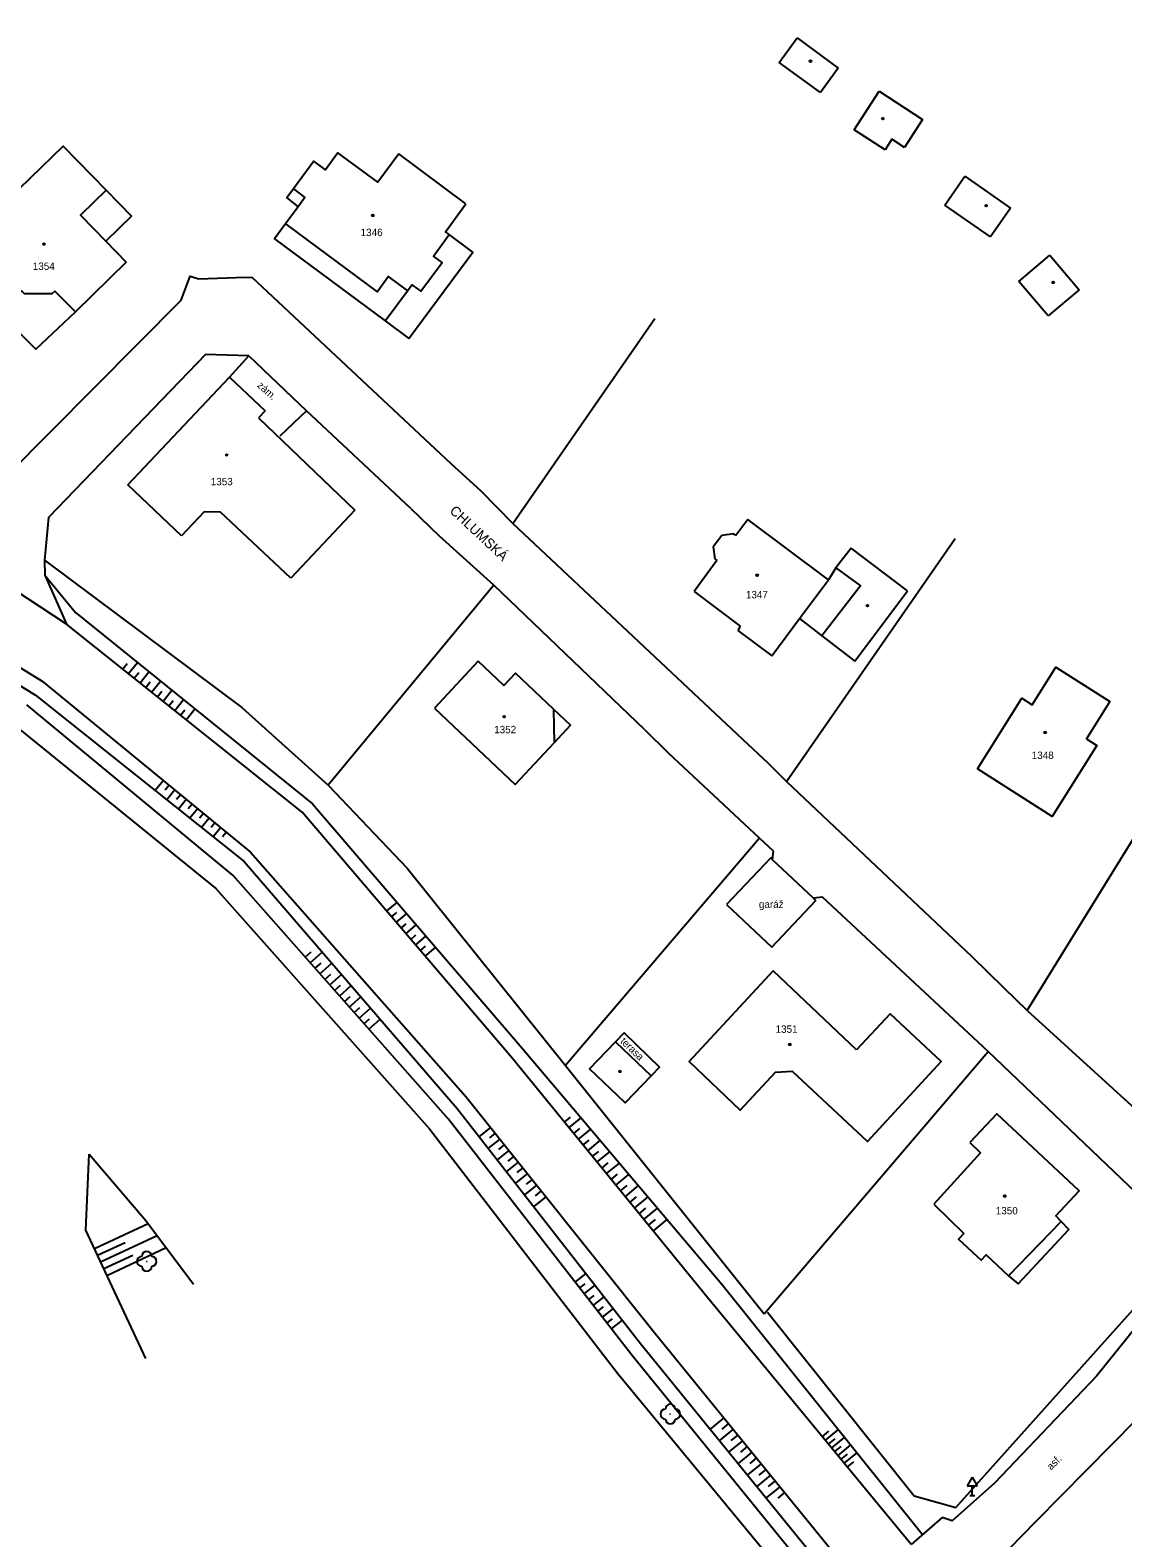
# Model space of a CAD drawing. Extents: x -794191 to -788944, y -1117087 to -1105044.
# Drawn here: x -792433.6 to -792322.7, y -1109251.7 to -1109098.8 of the extents above; entities that cross this region are included whole.
import ezdxf

# ---------------------------------------------------------------- set-up
doc = ezdxf.new("R2010")
doc.units = 0
for name, color, linetype in [('Doplňkové značky', 7, 'Continuous'), ('Hranice - ploty_ zdi', 7, 'Continuous'), ('Komunikace', 7, 'Continuous'), ('Názvy ulic_ silnic_ žel_', 7, 'Continuous'), ('Pomocné popisy', 7, 'Continuous'), ('Popisy budov', 7, 'Continuous'), ('Stavební objekty', 7, 'Continuous'), ('Výškopis', 7, 'Continuous'), ('Zeleň', 7, 'Continuous'), ('Značky druhů budov', 7, 'Continuous'), ('Čísla popisná', 7, 'Continuous')]:
    doc.layers.add(name, color=color, linetype=linetype)

msp = doc.modelspace()

# ---------------------------------------------------------------- linework, layer by layer
at = {"layer": 'Doplňkové značky'}
for p, q in [((-792337.99, -1109245.564), (-792338.49, -1109246.43)), ((-792338.49, -1109246.43), (-792337.49, -1109246.43)), ((-792337.99, -1109245.564), (-792337.49, -1109246.43)), ((-792337.99, -1109247.43), (-792337.99, -1109246.43)), ((-792338.24, -1109247.43), (-792337.74, -1109247.43))]:
    msp.add_line(p, q, dxfattribs=at)
at = {"layer": 'Hranice - ploty_ zdi'}
for p, q in [((-792416.47, -1109123.98), (-792412.69, -1109123.86)), ((-792384.6, -1109148.81), (-792370.19, -1109128.01)), ((-792413.37, -1109133.97), (-792411.38, -1109131.8)), ((-792390.89, -1109142.72), (-792387.85, -1109145.48)), ((-792387.85, -1109145.48), (-792384.6, -1109148.81)), ((-792394.94, -1109147.29), (-792392.04, -1109150.11)), ((-792384.6, -1109148.81), (-792361.29, -1109170.69)), ((-792386.55, -1109155.05), (-792392.04, -1109150.11)), ((-792356.84, -1109174.99), (-792339.72, -1109150.34)), ((-792332.43, -1109198.21), (-792314.33, -1109168.93)), ((-792371.26, -1109169.72), (-792368.8, -1109172.1)), ((-792361.29, -1109170.69), (-792358.7, -1109173.12)), ((-792359.57, -1109180.73), (-792368.8, -1109172.1)), ((-792358.7, -1109173.12), (-792356.84, -1109174.99)), ((-792356.84, -1109174.99), (-792338.03, -1109192.74)), ((-792359.57, -1109180.73), (-792379.27, -1109203.8)), ((-792358.17, -1109182.06), (-792359.57, -1109180.73)), ((-792358.27, -1109182.94), (-792358.17, -1109182.06)), ((-792354.11, -1109186.82), (-792358.27, -1109182.94)), ((-792353.19, -1109186.72), (-792354.11, -1109186.82)), ((-792336.37, -1109202.39), (-792353.19, -1109186.72)), ((-792362.92, -1109187.47), (-792358.33, -1109191.8)), ((-792338.03, -1109192.74), (-792334.83, -1109195.87)), ((-792334.83, -1109195.87), (-792332.43, -1109198.21)), ((-792332.43, -1109198.21), (-792319.56, -1109209.93)), ((-792359.09, -1109228.98), (-792336.37, -1109202.39)), ((-792379.27, -1109203.8), (-792359.09, -1109228.98))]:
    msp.add_line(p, q, dxfattribs=at)
for points in [[(-792435.9, -1109143.89), (-792418.26, -1109126.16), (-792417.35, -1109123.73), (-792416.47, -1109123.98)], [(-792412.69, -1109123.86), (-792411.09, -1109123.83), (-792390.89, -1109142.72)], [(-792411.38, -1109131.8), (-792415.78, -1109131.66), (-792431.74, -1109148.19), (-792432.13, -1109152.54)], [(-792394.94, -1109147.29), (-792405.54, -1109137.37), (-792408.24, -1109139.95)], [(-792432.13, -1109152.54), (-792412.1, -1109167.48), (-792403.34, -1109175.37)], [(-792371.26, -1109169.72), (-792386.55, -1109155.05), (-792403.34, -1109175.37)], [(-792403.34, -1109175.37), (-792395.34, -1109183.79), (-792379.27, -1109203.8)], [(-792358.27, -1109182.94), (-792358.44, -1109182.74), (-792362.92, -1109187.47)], [(-792358.33, -1109191.8), (-792353.9, -1109187.09), (-792354.11, -1109186.82)], [(-792374.18, -1109201.39), (-792373.3, -1109200.5), (-792369.71, -1109203.96), (-792370.56, -1109204.86)], [(-792317.22, -1109223.41), (-792316.83, -1109221.03), (-792336.37, -1109202.39)], [(-792358.77, -1109228.84), (-792343.87, -1109247.47), (-792339.66, -1109248.64), (-792319.89, -1109226.58)]]:
    msp.add_lwpolyline(points, dxfattribs=at)
at = {"layer": 'Komunikace'}
for p, q in [((-792411.38, -1109131.8), (-792405.54, -1109137.37)), ((-792447.38, -1109155.57), (-792432.36, -1109164.8)), ((-792432.36, -1109164.8), (-792411.21, -1109182.14)), ((-792411.21, -1109182.14), (-792389.39, -1109206.94)), ((-792315.92, -1109223.55), (-792325.38, -1109235.31))]:
    msp.add_line(p, q, dxfattribs=at)
for points in [[(-792344.2, -1109252.39), (-792364.9, -1109227.31), (-792384.65, -1109203.09), (-792405.99, -1109178.11), (-792429.89, -1109159.02), (-792436.53, -1109154.65), (-792444.12, -1109150.51), (-792463.48, -1109139.83), (-792485.49, -1109128.03), (-792502.16, -1109119.01), (-792513.91, -1109112.56), (-792525.39, -1109106.43), (-792542.08, -1109097.39), (-792570.53, -1109082.24), (-792594.12, -1109069.43), (-792609.89, -1109060.71), (-792628.36, -1109050.84), (-792647.56, -1109040.71)], [(-792432.13, -1109152.54), (-792432.1, -1109154.04), (-792429.89, -1109159.02)], [(-792389.39, -1109206.94), (-792370.12, -1109231.03), (-792348.83, -1109257.2), (-792332.86, -1109277.6), (-792324.34, -1109288.15)], [(-792337.34, -1109261.8), (-792337.76, -1109260.31), (-792337.77, -1109258.92), (-792337.53, -1109257.73), (-792336.95, -1109255.61), (-792331.49, -1109250.02), (-792321.28, -1109239.69), (-792309.93, -1109226.65), (-792306.29, -1109222.44)], [(-792325.38, -1109235.31), (-792335.73, -1109246.18), (-792340.01, -1109250), (-792341.03, -1109249.65), (-792344.2, -1109252.39)]]:
    msp.add_lwpolyline(points, dxfattribs=at)
at = {"layer": 'Stavební objekty'}
for p, q in [((-792357.58, -1109102.02), (-792355.77, -1109099.53)), ((-792355.77, -1109099.53), (-792351.58, -1109102.6)), ((-792353.39, -1109105.07), (-792357.58, -1109102.02)), ((-792351.58, -1109102.6), (-792353.39, -1109105.07)), ((-792349.97, -1109108.86), (-792347.44, -1109104.96)), ((-792347.44, -1109104.96), (-792343.03, -1109107.83)), ((-792346.84, -1109110.89), (-792349.97, -1109108.86)), ((-792343.03, -1109107.83), (-792344.86, -1109110.65)), ((-792346.14, -1109109.81), (-792346.84, -1109110.89)), ((-792344.86, -1109110.65), (-792346.14, -1109109.81)), ((-792340.77, -1109116.52), (-792338.73, -1109113.56)), ((-792338.73, -1109113.56), (-792334.1, -1109116.81)), ((-792425.87, -1109114.98), (-792423.31, -1109117.62)), ((-792336.14, -1109119.71), (-792340.77, -1109116.52)), ((-792334.1, -1109116.81), (-792336.14, -1109119.71)), ((-792333.26, -1109124.26), (-792330.13, -1109121.57)), ((-792330.13, -1109121.57), (-792327.15, -1109125.09)), ((-792330.27, -1109127.73), (-792333.26, -1109124.26)), ((-792327.15, -1109125.09), (-792330.27, -1109127.73)), ((-792397.56, -1109128.23), (-792395.16, -1109130.03)), ((-792423.67, -1109144.88), (-792413.37, -1109133.97)), ((-792413.37, -1109133.97), (-792409.75, -1109137.39)), ((-792409.75, -1109137.39), (-792410.42, -1109138.09)), ((-792410.42, -1109138.09), (-792400.65, -1109147.44)), ((-792418.22, -1109150.05), (-792423.67, -1109144.88)), ((-792400.65, -1109147.44), (-792407.15, -1109154.37)), ((-792415.93, -1109147.62), (-792418.22, -1109150.05)), ((-792414.26, -1109147.65), (-792415.93, -1109147.62)), ((-792407.15, -1109154.37), (-792414.26, -1109147.65)), ((-792360.75, -1109148.4), (-792361.99, -1109150.04)), ((-792352.56, -1109154.51), (-792360.75, -1109148.4)), ((-792363.41, -1109150.04), (-792364.29, -1109151.18)), ((-792362.17, -1109149.87), (-792363.41, -1109150.04)), ((-792361.99, -1109150.04), (-792362.17, -1109149.87)), ((-792364.29, -1109151.18), (-792364.1, -1109152.41)), ((-792350.27, -1109151.3), (-792351.84, -1109153.31)), ((-792344.56, -1109155.65), (-792350.27, -1109151.3)), ((-792363.92, -1109152.56), (-792366.22, -1109155.71)), ((-792364.1, -1109152.41), (-792363.92, -1109152.56)), ((-792351.84, -1109153.31), (-792352.56, -1109154.51)), ((-792355.5, -1109158.46), (-792352.56, -1109154.51)), ((-792366.22, -1109155.71), (-792361.53, -1109159.23)), ((-792349.89, -1109162.76), (-792344.56, -1109155.65)), ((-792361.53, -1109159.23), (-792361.78, -1109159.67)), ((-792361.78, -1109159.67), (-792358.31, -1109162.25)), ((-792358.31, -1109162.25), (-792355.5, -1109158.46)), ((-792355.5, -1109158.46), (-792353.25, -1109160.22)), ((-792353.25, -1109160.22), (-792349.89, -1109162.76)), ((-792380.48, -1109167.63), (-792380.4, -1109171.05)), ((-792374.18, -1109201.39), (-792370.56, -1109204.86))]:
    msp.add_line(p, q, dxfattribs=at)
for points in [[(-792423.83, -1109122.29), (-792428.99, -1109127.35), (-792431.09, -1109125.24), (-792431.4, -1109125.5), (-792434.15, -1109125.51), (-792434.48, -1109125.21), (-792436.77, -1109127.44), (-792440.51, -1109123.66), (-792439.92, -1109123.03), (-792437.74, -1109120.94), (-792438.5, -1109120.15), (-792434.99, -1109116.7), (-792435.78, -1109115.91), (-792430.23, -1109110.53), (-792425.87, -1109114.98), (-792428.48, -1109117.51), (-792425.91, -1109120.15)], [(-792396.19, -1109111.32), (-792398.3, -1109114.17), (-792402.35, -1109111.19), (-792403.62, -1109112.91), (-792404.8, -1109112.05), (-792406.88, -1109114.87), (-792405.71, -1109115.75), (-792406.4, -1109116.69), (-792407.68, -1109118.42), (-792398.39, -1109125.29), (-792397.25, -1109123.76), (-792395.29, -1109125.21), (-792394.84, -1109124.59), (-792393.94, -1109125.24), (-792391.79, -1109122.32), (-792392.64, -1109121.68), (-792391.07, -1109119.5), (-792391.44, -1109119.21), (-792389.37, -1109116.38)], [(-792389.37, -1109116.38), (-792396.19, -1109111.32)], [(-792406.88, -1109114.87), (-792407.54, -1109115.78), (-792406.4, -1109116.69)], [(-792423.31, -1109117.62), (-792425.91, -1109120.15), (-792423.83, -1109122.29)], [(-792407.68, -1109118.42), (-792408.8, -1109119.94), (-792397.56, -1109128.23), (-792395.29, -1109125.21)], [(-792395.16, -1109130.03), (-792388.68, -1109121.27), (-792391.07, -1109119.5)], [(-792436.77, -1109127.44), (-792433, -1109131.11), (-792428.99, -1109127.35)], [(-792351.84, -1109153.31), (-792349.33, -1109155.12), (-792353.25, -1109160.22)], [(-792388.14, -1109162.79), (-792392.56, -1109167.54)], [(-792392.56, -1109167.54), (-792384.37, -1109175.28), (-792380.4, -1109171.05), (-792378.74, -1109169.27), (-792380.48, -1109167.63), (-792384.35, -1109164.01), (-792385.52, -1109165.23), (-792388.14, -1109162.79)], [(-792358.18, -1109194.21), (-792366.7, -1109203.4), (-792361.55, -1109208.32), (-792357.94, -1109204.46), (-792356.26, -1109204.39), (-792348.63, -1109211.52), (-792341.13, -1109203.38), (-792346.32, -1109198.57), (-792349.72, -1109202.22)], [(-792349.72, -1109202.22), (-792358.18, -1109194.21)], [(-792370.56, -1109204.86), (-792373.22, -1109207.59), (-792376.83, -1109204.13), (-792374.18, -1109201.39)], [(-792341.9, -1109217.86), (-792338.85, -1109220.85), (-792339.37, -1109221.41), (-792337.07, -1109223.56), (-792336.56, -1109223.02), (-792334.3, -1109225.15), (-792333.32, -1109225.95), (-792328.17, -1109220.45), (-792328.98, -1109219.61), (-792329.52, -1109219.05), (-792327.13, -1109216.51), (-792335.49, -1109208.69), (-792338.23, -1109211.6)], [(-792338.23, -1109211.6), (-792337.14, -1109212.65), (-792341.9, -1109217.86)], [(-792334.3, -1109225.15), (-792328.98, -1109219.61)]]:
    msp.add_lwpolyline(points, dxfattribs=at)
msp.add_lwpolyline([(-792337.47, -1109173.71), (-792332.96, -1109166.54), (-792331.9, -1109167.19), (-792329.5, -1109163.38), (-792324.02, -1109166.87), (-792326.4, -1109170.67), (-792325.36, -1109171.34), (-792329.89, -1109178.53)], close=True, dxfattribs=at)
at = {"layer": 'Výškopis'}
for p, q in [((-792448.18, -1109156.9), (-792433.05, -1109166.21)), ((-792424.19, -1109163.57), (-792423.74, -1109163)), ((-792423.61, -1109164.04), (-792422.7, -1109162.91)), ((-792423.02, -1109164.51), (-792422.57, -1109163.94)), ((-792422.43, -1109164.97), (-792421.54, -1109163.85)), ((-792421.85, -1109165.44), (-792421.4, -1109164.88)), ((-792421.26, -1109165.91), (-792420.37, -1109164.79)), ((-792420.68, -1109166.38), (-792420.23, -1109165.82)), ((-792420.09, -1109166.85), (-792419.2, -1109165.73)), ((-792413, -1109184.53), (-792433.93, -1109167.21)), ((-792433.05, -1109166.21), (-792411.87, -1109183.11)), ((-792419.5, -1109167.31), (-792419.06, -1109166.76)), ((-792418.92, -1109167.78), (-792418.03, -1109166.67)), ((-792418.33, -1109168.25), (-792417.89, -1109167.7)), ((-792417.75, -1109168.72), (-792416.87, -1109167.62)), ((-792420.05, -1109174.89), (-792420.89, -1109175.91)), ((-792419.47, -1109175.37), (-792419.89, -1109175.87)), ((-792418.89, -1109175.84), (-792419.72, -1109176.85)), ((-792418.31, -1109176.32), (-792418.72, -1109176.82)), ((-792417.73, -1109176.79), (-792418.54, -1109177.78)), ((-792417.15, -1109177.27), (-792417.55, -1109177.76)), ((-792416.57, -1109177.74), (-792417.37, -1109178.72)), ((-792415.99, -1109178.22), (-792416.39, -1109178.7)), ((-792415.41, -1109178.69), (-792416.2, -1109179.66)), ((-792414.83, -1109179.17), (-792415.22, -1109179.65)), ((-792414.25, -1109179.65), (-792415.03, -1109180.59)), ((-792413.67, -1109180.12), (-792414.06, -1109180.59)), ((-792411.87, -1109183.11), (-792390.25, -1109208.16)), ((-792391.17, -1109209.22), (-792413, -1109184.53)), ((-792397.41, -1109188.15), (-792396.35, -1109187.25)), ((-792396.92, -1109188.73), (-792396.39, -1109188.27)), ((-792396.43, -1109189.29), (-792395.37, -1109188.39)), ((-792395.95, -1109189.87), (-792395.42, -1109189.41)), ((-792395.46, -1109190.44), (-792394.4, -1109189.53)), ((-792394.97, -1109191.01), (-792394.44, -1109190.55)), ((-792394.49, -1109191.58), (-792393.42, -1109190.67)), ((-792394, -1109192.15), (-792393.47, -1109191.69)), ((-792393.51, -1109192.72), (-792392.44, -1109191.81)), ((-792405.67, -1109192.81), (-792405.06, -1109192.27)), ((-792405.18, -1109193.38), (-792403.95, -1109192.29)), ((-792404.68, -1109193.94), (-792404.07, -1109193.4)), ((-792404.19, -1109194.5), (-792402.97, -1109193.42)), ((-792403.69, -1109195.06), (-792403.08, -1109194.53)), ((-792403.19, -1109195.62), (-792401.99, -1109194.56)), ((-792402.69, -1109196.19), (-792402.1, -1109195.66)), ((-792402.2, -1109196.75), (-792401.01, -1109195.69)), ((-792401.7, -1109197.31), (-792401.11, -1109196.79)), ((-792401.2, -1109197.87), (-792400.03, -1109196.83)), ((-792400.71, -1109198.43), (-792400.12, -1109197.92)), ((-792400.21, -1109198.99), (-792399.05, -1109197.97)), ((-792399.71, -1109199.56), (-792399.14, -1109199.05)), ((-792399.22, -1109200.12), (-792398.07, -1109199.1)), ((-792390.25, -1109208.16), (-792371.65, -1109231.99)), ((-792372.39, -1109233.34), (-792391.17, -1109209.22)), ((-792386.87, -1109210.09), (-792388.03, -1109211.01)), ((-792379.38, -1109209.55), (-792378.77, -1109209.05)), ((-792378.91, -1109210.13), (-792377.67, -1109209.12)), ((-792378.43, -1109210.71), (-792377.81, -1109210.2)), ((-792385.93, -1109211.26), (-792387.1, -1109212.19)), ((-792386.4, -1109210.67), (-792386.98, -1109211.14)), ((-792377.96, -1109211.29), (-792376.7, -1109210.27)), ((-792377.49, -1109211.87), (-792376.85, -1109211.36)), ((-792377.01, -1109212.45), (-792375.73, -1109211.41)), ((-792427.94, -1109220.52), (-792427.6, -1109212.81)), ((-792427.6, -1109212.81), (-792421.84, -1109219.53)), ((-792385, -1109212.43), (-792386.18, -1109213.37)), ((-792385.47, -1109211.84), (-792386.05, -1109212.31)), ((-792384.53, -1109213.02), (-792385.12, -1109213.49)), ((-792376.54, -1109213.04), (-792375.89, -1109212.51)), ((-792376.07, -1109213.62), (-792374.77, -1109212.56)), ((-792384.06, -1109213.6), (-792385.26, -1109214.56)), ((-792383.12, -1109214.77), (-792384.33, -1109215.74)), ((-792383.59, -1109214.19), (-792384.19, -1109214.67)), ((-792375.59, -1109214.2), (-792374.94, -1109213.66)), ((-792375.12, -1109214.78), (-792373.79, -1109213.7)), ((-792374.64, -1109215.36), (-792373.98, -1109214.82)), ((-792382.19, -1109215.94), (-792383.41, -1109216.92)), ((-792382.66, -1109215.36), (-792383.26, -1109215.85)), ((-792374.17, -1109215.94), (-792372.83, -1109214.85)), ((-792373.69, -1109216.52), (-792373.02, -1109215.97)), ((-792373.22, -1109217.11), (-792371.86, -1109215.99)), ((-792381.25, -1109217.12), (-792382.49, -1109218.11)), ((-792381.72, -1109216.53), (-792382.33, -1109217.02)), ((-792372.75, -1109217.69), (-792372.06, -1109217.13)), ((-792372.27, -1109218.27), (-792370.89, -1109217.14)), ((-792371.8, -1109218.85), (-792371.1, -1109218.28)), ((-792371.33, -1109219.43), (-792369.92, -1109218.28)), ((-792421.85, -1109233.54), (-792427.94, -1109220.52)), ((-792427.07, -1109222.37), (-792421.62, -1109219.82)), ((-792421.84, -1109219.53), (-792417, -1109225.98)), ((-792370.85, -1109220.01), (-792370.14, -1109219.43)), ((-792370.38, -1109220.59), (-792368.95, -1109219.43)), ((-792426.76, -1109223.05), (-792423.96, -1109221.74)), ((-792426.44, -1109223.73), (-792420.7, -1109221.05)), ((-792425.8, -1109225.09), (-792419.78, -1109222.27)), ((-792426.12, -1109224.41), (-792423.18, -1109223.04)), ((-792378.28, -1109225.78), (-792377.17, -1109224.91)), ((-792377.82, -1109226.37), (-792377.26, -1109225.94)), ((-792377.36, -1109226.96), (-792376.25, -1109226.1)), ((-792376.9, -1109227.55), (-792376.34, -1109227.12)), ((-792376.44, -1109228.14), (-792375.33, -1109227.28)), ((-792375.97, -1109228.74), (-792375.42, -1109228.3)), ((-792375.51, -1109229.33), (-792374.4, -1109228.46)), ((-792375.05, -1109229.92), (-792374.5, -1109229.49)), ((-792374.59, -1109230.51), (-792373.48, -1109229.65)), ((-792371.65, -1109231.99), (-792350.09, -1109258.51)), ((-792351.23, -1109259.36), (-792372.39, -1109233.34)), ((-792363.19, -1109239.55), (-792364.58, -1109240.69)), ((-792362.24, -1109240.71), (-792363.63, -1109241.85)), ((-792362.71, -1109240.13), (-792363.41, -1109240.7)), ((-792352.9, -1109241.85), (-792351.56, -1109240.74)), ((-792361.29, -1109241.88), (-792362.69, -1109243.01)), ((-792361.77, -1109241.3), (-792362.47, -1109241.86)), ((-792353.22, -1109241.46), (-792352.54, -1109240.9)), ((-792352.58, -1109242.23), (-792351.91, -1109241.68)), ((-792352.26, -1109242.62), (-792350.93, -1109241.52)), ((-792351.63, -1109243.39), (-792350.3, -1109242.3)), ((-792360.35, -1109243.04), (-792361.74, -1109244.18)), ((-792360.82, -1109242.46), (-792361.52, -1109243.03)), ((-792359.87, -1109243.62), (-792360.57, -1109244.19)), ((-792351.95, -1109243), (-792351.28, -1109242.46)), ((-792351.31, -1109243.78), (-792350.65, -1109243.23)), ((-792350.99, -1109244.16), (-792349.68, -1109243.08)), ((-792359.4, -1109244.21), (-792360.8, -1109245.34)), ((-792358.45, -1109245.37), (-792359.85, -1109246.5)), ((-792358.93, -1109244.79), (-792359.63, -1109245.35)), ((-792350.67, -1109244.55), (-792350.02, -1109244.01)), ((-792357.51, -1109246.53), (-792358.9, -1109247.67)), ((-792357.98, -1109245.95), (-792358.68, -1109246.52)), ((-792357.03, -1109247.11), (-792357.73, -1109247.68))]:
    msp.add_line(p, q, dxfattribs=at)
msp.add_lwpolyline([(-792432.1, -1109154.04), (-792428.99, -1109157.84), (-792404.93, -1109177.24), (-792383.67, -1109202.04), (-792363.39, -1109225.99), (-792343.02, -1109251.37)], dxfattribs=at)
at = {"layer": 'Zeleň'}
for p, q in [((-792435.9, -1109168.68), (-792414.75, -1109185.85)), ((-792414.75, -1109185.85), (-792393.07, -1109210.23)), ((-792393.07, -1109210.23), (-792373.97, -1109235.01)), ((-792373.97, -1109235.01), (-792352.7, -1109260.78))]:
    msp.add_line(p, q, dxfattribs=at)
for centre in [(-792421.75, -1109223.67), (-792368.63, -1109239.17)]:
    msp.add_circle(centre, 0.0005, dxfattribs=at)
for centre, start, end in [((-792422.25, -1109223.67), 89.99999, 269.99999), ((-792421.75, -1109223.17), 0, 179.99999), ((-792421.25, -1109223.67), 270, 89.99999), ((-792421.75, -1109224.17), 179.99999, 359.99999), ((-792369.13, -1109239.17), 89.99999, 269.99999), ((-792368.63, -1109238.67), 0, 179.99999), ((-792368.13, -1109239.17), 270, 89.99999), ((-792368.63, -1109239.67), 179.99999, 359.99999)]:
    msp.add_arc(centre, 0.5, start, end, dxfattribs=at)
at = {"layer": 'Značky druhů budov'}
for centre in [(-792354.4, -1109101.9), (-792347.06, -1109107.74), (-792336.58, -1109116.56), (-792398.81, -1109117.55), (-792432.18, -1109120.46), (-792329.77, -1109124.35), (-792413.64, -1109141.86), (-792359.81, -1109154.06), (-792348.62, -1109157.14), (-792385.49, -1109168.41), (-792330.59, -1109170.01), (-792356.5, -1109201.66), (-792373.73, -1109204.4), (-792334.69, -1109217.05)]:
    msp.add_circle(centre, 0.0875, dxfattribs=at)

# ---------------------------------------------------------------- texts
at = {"layer": 'Názvy ulic_ silnic_ žel_'}
msp.add_text('CHLUMSKÁ', height=1, rotation=316.83879, dxfattribs=at).set_placement((-792391.09, -1109147.62))
at = {"layer": 'Pomocné popisy'}
for s, rotation, p in [('zám.', 318.48028, (-792410.609, -1109134.892)), ('terasa', 316.212, (-792373.76, -1109201.42)), ('asf.', 45.43529, (-792329.98, -1109244.91))]:
    msp.add_text(s, height=0.75, rotation=rotation, dxfattribs=at).set_placement(p)
at = {"layer": 'Popisy budov'}
msp.add_text('garáž', height=0.75, dxfattribs=at).set_placement((-792359.638, -1109187.81))
at = {"layer": 'Čísla popisná'}
for s, p in [('1346', (-792400.05, -1109119.65)), ('1354', (-792433.32, -1109123.08)), ('1353', (-792415.26, -1109144.93)), ('1347', (-792360.954, -1109156.4)), ('1352', (-792386.5, -1109170.09)), ('1348', (-792331.95, -1109172.7)), ('1351', (-792357.94, -1109200.48)), ('1350', (-792335.6, -1109218.9))]:
    msp.add_text(s, height=0.75, dxfattribs=at).set_placement(p)

doc.saveas('drawing.dxf')
